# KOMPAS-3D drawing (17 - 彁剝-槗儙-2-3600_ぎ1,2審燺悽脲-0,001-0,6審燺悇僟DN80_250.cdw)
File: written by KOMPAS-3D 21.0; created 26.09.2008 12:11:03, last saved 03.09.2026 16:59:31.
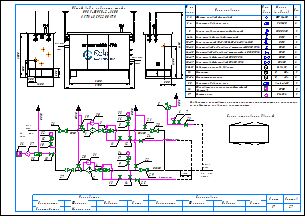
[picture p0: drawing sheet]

Sheets 1-2: A3, landscape

Document properties: Наименование: Макро:21; Автор: RaskoAdmin; Форматы листов документа: 2xA3; Полное имя файла: \\UR38nt01\Departments\КТО\КБ ПУРДГ\Заявки\Прайс-лист на типовые шкафы ГРПШ\ПРДГ_стандарт_20_03_2026\ПРДГ с РДГ(Н, В)\ПРДГ-ШУГО-2-3600_до1,2МПа_Рвых-0,001-0,6МПа_РДГ_DN80_250.cdw

Title block, sheet 1: Наименование: Пункт учета газа / ПУГ-Ш-400-Р / ЛГТИ.485922.001ТУ; designation: ЛГТИ.03.4411141; sheet number: 1; Количество листов документа: 2; organisation: ООО "ЭЛЬСТЕР Газэлектроника"; Форматы листов документа: A3; stored path: C:\Рабочие документы\Компас\ПУГ\Схема.cdw; Разработал: Устинов; Проверил: Кошкин; Утвердил: Кошкин
Title block, sheet 2: sheet number: 2; stored path: D:\Рабочие документы\Заявки\ПУРДГ\ПУРДГ-ШУЭО-2-100-Р 4411220.cdw; designation, second copy: ЛГТИ.03.4411141-

Views: Вид 1, Вид 2
Referenced files: wcvoit.frw
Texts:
  Normal
  Общий вид и габариты шкафа
  ПРДГ-ШУГО-2-3600
  DN250
  Выход газа
  DN80
  Вход газа
  logo-rasko-ge.png
  Вход
  газа
  PDI
  Выход
  Р=     кПа
  DN50
  DN25
  DN20
  Импульс DN20
  ≥5DN
  HYSWLongFangSong
  Р=       МПа
  № на
  схеме
  Усл.
  обозн.
  Марка
  (модель)
  Кол.
  Фильтр газовый фланцевый
  ФГ 16-80
  Регулятор давления газа
  РДГ-50
  Клапан предохранительный сбросной
  КПС DN20
  Кран шаровой газовый латунный
  DN15
  Кран кнопочный VE-РАСКО-НЗ-1,6-G1/2-М20
  Кран шаровой "под приварку" штуцерный DN20 PN16
  Кран шаровой "под приварку" штуцерный п/п DN20 PN16
  Кран шаровой фланцевый DN80 PN16
  Кран шаровой фланцевый DN250 PN16
  Индикатор перепада давления
  Delta 15
  Манометр
  Манометр-напоромер
  0...     МПа
  0...     кПа
  Обогреватель газогорелочный шкафной
  (Эльтон")
  Счетчик газа
  Venio-A-15
  ОГШН
  BK-G1,6
  Схема открывания дверей
  Предприятие изготовитель может заменять комплектующие на аналогичные,
  не ухудшающие заявленных характеристик.
  Должность
  Конструктор
  Фамилия
  Подпись
  Дата
  Согласовано
  Максимкин
  Лист
  Листов
  POLYLINE_STYLE_0.18_RGB_0_0_0
  POLYLINE_STYLE_0.50_RGB_0_0_0
  POLYLINE_STYLE_0.34_RGB_0_0_0
  PHANTOM_RGB_0_0_0_SC_1_THICK_0.18
  K5LT_THIN_RGB_0_0_0_THICK_0.18
  K5LT32769_RGB_0_0_0_THICK_0.18
  K5LT12_RGB_0_0_0_SC_1_THICK_0.18
  K5LT_DASHED_RGB_0_0_0_SC_1_THICK_0.18
  ACISOTGL_RGB_0_0_0_SC_0.8_THICK_0.25
  CONTINUOUS_RGB_0_127_31_THICK_0.3
  CONTINUOUS_RGB_0_0_255_THICK_0.35
  CONTINUOUS_RGB_255_0_0_THICK_0.35
  POLYLINE_STYLE_0.25_RGB_0_0_0
  CONTINUOUS_RGB_0_0_0_THICK_0.5
  POLYLINE_STYLE_0.35_RGB_0_0_255
  CONTINUOUS_RGB_0_0_0_THICK_0.4
  CONTINUOUS_RGB_0_0_0_THICK_0.35
  Без оформления
Dimensions and other numbers on the sheet: 1; 500; 1200; 305; 2000; 3900; 4130; 3600; 2; 3; 4; 5; 10; 27; 28; 29; 23; 8; 12; 19; 20; 21; 22; 25; 24; 30; 31; 15; 16; 32; 26; 6; 7; 11; 14; 13; 33; 9; 17; 34; 18; 35; 36; 37; 1, 2; 3, 4; 6-14; 15-17; 18-23; 24-25; 26-27; 28-29; 30-31; 33-34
